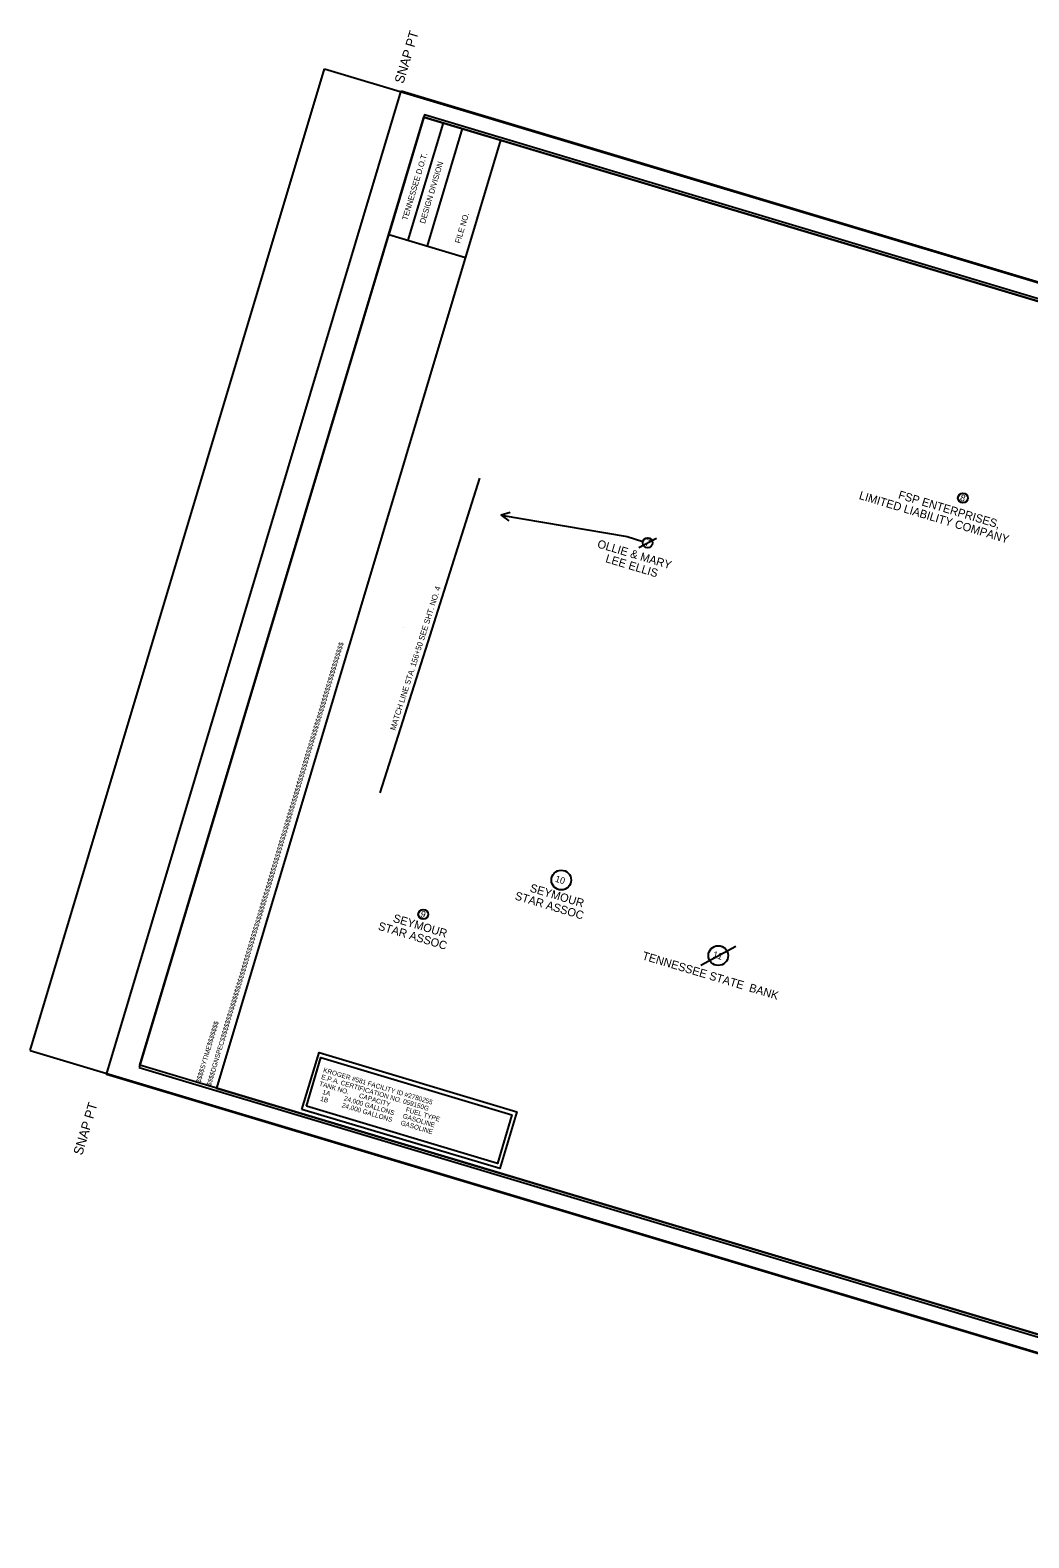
# Model space of a CAD drawing. Extents: x 2627582 to 2629622, y 568931 to 570612.
# Drawn here: x 2627582 to 2628642, y 569012 to 570612 of the extents above; entities that cross this region are included whole.
import ezdxf

# ---------------------------------------------------------------- set-up
doc = ezdxf.new("R2010")
doc.units = 0
for name, color, linetype in [('DESIGN - CENTERLINE - Proposed Text', 7, 'Continuous'), ('DESIGN - SCRATCH - User 1', 7, 'Continuous'), ('DESIGN - SHEET - Corner Text', 7, 'Continuous'), ('DESIGN - SHEET - Light Grid', 7, 'Continuous'), ('DESIGN - SHEET - Linework', 7, 'Continuous'), ('DESIGN - SHEET - Plot Shape', 7, 'Continuous'), ('SURVEY - PROJECT INFORMATION and NOTES', 7, 'Continuous'), ('SURVEY - PROPERTY - Owners', 7, 'Continuous'), ('SURVEY - PROPERTY - Tract Numbers', 7, 'Continuous')]:
    doc.layers.add(name, color=color, linetype=linetype)

msp = doc.modelspace()

# ---------------------------------------------------------------- linework, layer by layer
at = {"layer": 'DESIGN - CENTERLINE - Proposed Text'}
msp.add_lwpolyline([(2627953.5, 569802.8), (2628006.4, 569969.6), (2628059.3, 570136.4)], dxfattribs=at)
at = {"layer": 'DESIGN - SCRATCH - User 1'}
msp.add_line((2627978.5, 569977.9), (2627978.5, 569977.9), dxfattribs=at)
at = {"layer": 'DESIGN - SHEET - Light Grid'}
msp.add_lwpolyline([(2627697.6, 569511.4), (2629292.5, 569033.3), (2629595.5, 570043.9), (2628000.6, 570522)], close=True, dxfattribs=at)
at = {"layer": 'DESIGN - SHEET - Linework'}
for p, q in [((2627582.1, 569529.2), (2627894.3, 570570.8)), ((2627894.3, 570570.8), (2629618.5, 570053.9)), ((2628020.2, 570513.5), (2627982.9, 570389.1)), ((2628040.6, 570507.4), (2628003.3, 570383)), ((2627582.1, 569529.2), (2629306.3, 569012.3))]:
    msp.add_line(p, q, dxfattribs=at)
for points in [[(2628081.3, 570495.2), (2627999.9, 570519.6), (2627962.6, 570395.2), (2628044, 570370.8)], [(2628081.3, 570495.2), (2627779.8, 569489.4), (2629287.7, 569037.4), (2629589.2, 570043.2), (2628081.3, 570495.2)]]:
    msp.add_lwpolyline(points, dxfattribs=at)
at = {"layer": 'DESIGN - SHEET - Plot Shape'}
for points in [[(2627975.9, 570547.4), (2629604.3, 570059.2), (2629291.5, 569015.7), (2627663.1, 569503.8)], [(2627999.9, 570519.6), (2629589.2, 570043.2), (2629287.7, 569037.4), (2627698.4, 569513.8)]]:
    msp.add_lwpolyline(points, close=True, dxfattribs=at)
at = {"layer": 'SURVEY - PROJECT INFORMATION and NOTES'}
for points in [[(2627870.5, 569466.9), (2627888.6, 569527.3), (2628098.5, 569464.3), (2628080.4, 569404)], [(2627875.2, 569470.2), (2627890.7, 569521.9), (2628093.3, 569461.2), (2628077.8, 569409.5)]]:
    msp.add_lwpolyline(points, close=True, dxfattribs=at)
at = {"layer": 'SURVEY - PROPERTY - Tract Numbers'}
for p, q in [((2628228.1, 570063), (2628246.6, 570073)), ((2628293.7, 569620), (2628330.7, 569640))]:
    msp.add_line(p, q, dxfattribs=at)
for points in [[(2628091.4, 570100), (2628082, 570097.2), (2628089.9, 570091.4)], [(2628082, 570097.2), (2628215.5, 570074.5)], [(2628215.5, 570074.5), (2628232.3, 570069.5)]]:
    msp.add_lwpolyline(points, dxfattribs=at)
for centre, radius in [((2628571.8, 570115.5), 5.25), ((2628237.3, 570068), 5.25), ((2628145.6, 569710.2), 10.5), ((2627999.2, 569673.8), 5.25), ((2628312.2, 569630), 10.5)]:
    msp.add_circle(centre, radius, dxfattribs=at)

# ---------------------------------------------------------------- texts
at = {"layer": 'DESIGN - CENTERLINE - Proposed Text'}
msp.add_text('MATCH LINE STA. 156+50 SEE SHT. NO. 4', height=6, rotation=72.3958, dxfattribs=at).set_placement((2627969.5, 569868.4))
at = {"layer": 'DESIGN - SHEET - Corner Text'}
for s, height, p in [('  SNAP PT', 10, (2627975.9, 570547.4)), ('TENNESSEE D.O.T.', 6, (2627982.3, 570409.6)), ('DESIGN DIVISION', 6, (2628001, 570406.1)), ('FILE NO.', 6, (2628038.3, 570385.1)), ('$$$$DGNSPEC$$$$$$$$$$$$$$$$$$$$$$$$$$$$$$$$$$$$$$$$$$$$$$$$$$$$$$$$$$$$$$$$$$$$$$$$$$$$$$$$$$$$$$$$$$$$$$$$$$$$$$$$$$$$$$$$$$$', 5.0001, (2627773.8, 569491.2)), ('$$$$SYTIME$$$$$$$', 5, (2627762.7, 569494.5)), ('SNAP PT  ', 10, (2627637.3, 569417.6))]:
    msp.add_text(s, height=height, rotation=73.3133, dxfattribs=at).set_placement(p)
at = {"layer": 'SURVEY - PROJECT INFORMATION and NOTES'}
for s, p in [('KROGER #581 FACILITY ID #2780255', (2627892.6, 569506.5)), ('TANK NO.      CAPACITY         FUEL TYPE', (2627888.3, 569492.1)), ('E.P.A. CERTIFICATION NO. 059150G', (2627890.5, 569499.3)), ('   1B        24,000 GALLONS     GASOLINE', (2627884, 569477.8)), ('   1A        24,000 GALLONS     GASOLINE', (2627886.2, 569485))]:
    msp.add_text(s, height=5, rotation=343.3133, dxfattribs=at).set_placement(p)
at = {"layer": 'SURVEY - PROPERTY - Owners'}
for s, p in [('LIMITED LIABILITY COMPANY', (2628460.9, 570114.6)), ('FSP ENTERPRISES,', (2628502.5, 570115.2)), ('OLLIE & MARY', (2628183.2, 570063.2)), ('LEE ELLIS', (2628191.9, 570047.6)), ('STAR ASSOC', (2628095.7, 569689.8)), ('SEYMOUR', (2628111.6, 569698.1)), ('STAR ASSOC', (2627950.6, 569657.7)), ('SEYMOUR', (2627966.4, 569666)), ('TENNESSEE STATE  BANK', (2628230.8, 569626.2))]:
    msp.add_text(s, height=8.75, rotation=343.3133, dxfattribs=at).set_placement(p)
at = {"layer": 'SURVEY - PROPERTY - Tract Numbers'}
for s, p in [('8', (2628568.2, 570112.9)), ('7', (2628233.8, 570065.4)), ('10', (2628138.5, 569708.6)), ('9', (2627995.6, 569671.2)), ('11', (2628305.7, 569628.3))]:
    msp.add_text(s, height=7, rotation=343.3133, dxfattribs=at).set_placement(p)

doc.saveas('drawing.dxf')
